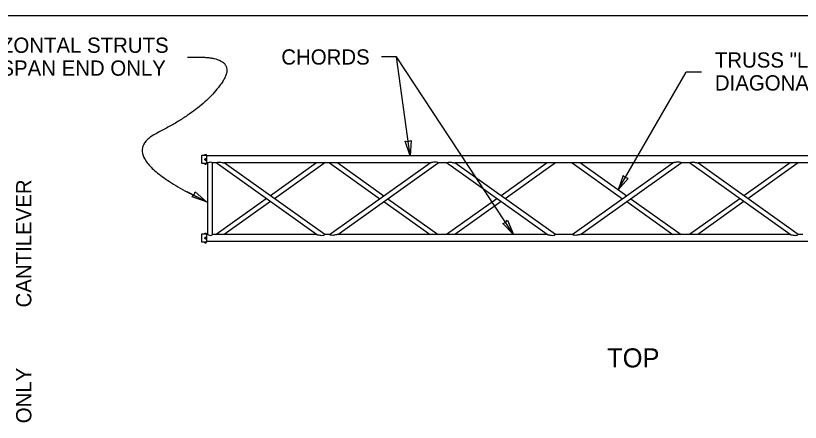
# Model space of a CAD drawing. Extents: x 99862 to 104211, y 98939 to 111076.
# Drawn here: x 100725 to 101548, y 101648 to 102075 of the extents above; entities that cross this region are included whole.
import ezdxf

# ---------------------------------------------------------------- set-up
doc = ezdxf.new("R2010")
doc.units = 0
for name, color, linetype in [('Level 14', 7, 'Continuous'), ('Level 15', 7, 'Continuous'), ('Level 20', 7, 'Continuous'), ('Level 6', 7, 'Continuous'), ('Level 60', 7, 'Continuous'), ('Level 62', 7, 'Continuous'), ('Level 9', 7, 'Continuous')]:
    doc.layers.add(name, color=color, linetype=linetype)

msp = doc.modelspace()

# ---------------------------------------------------------------- linework, layer by layer
at = {"layer": 'Level 14'}
msp.add_line((100905.36, 102031.62), (100913.36, 102031.62), dxfattribs=at)
msp.add_open_spline([(100913.36, 102031.62), (100960.09, 102032.22), (100921.98, 101976.24), (100824.85, 101927.65), (100925.31, 101879.73)], degree=2, dxfattribs=at)
at = {"layer": 'Level 15'}
for p, q in [((101124.65, 102031.68), (101108.65, 102031.68)), ((101138.85, 101927.97), (101124.65, 102031.68)), ((101247.26, 101845.47), (101124.65, 102031.68)), ((101357.15, 101892.22), (101428.52, 102015.84)), ((101444.52, 102015.84), (101428.52, 102015.84)), ((100926.54, 101879.04), (100904.98, 101890.24))]:
    msp.add_line(p, q, dxfattribs=at)
for points in [[(101138.85, 101927.97), (101133.77, 101943.17), (101136.92, 101942.84), (101139.89, 101943.96)], [(101357.15, 101892.22), (101367.69, 101904.3), (101364.65, 101905.21), (101362.34, 101907.38)], [(100925.31, 101879.73), (100910.15, 101884.92), (100912.32, 101887.23), (100913.23, 101890.26)], [(101247.26, 101845.47), (101235.99, 101856.86), (101238.96, 101857.96), (101241.13, 101860.27)]]:
    msp.add_lwpolyline(points, close=True, dxfattribs=at)
at = {"layer": 'Level 6'}
for p, q in [((100920.37, 101919.84), (100920.37, 101928.59)), ((100920.37, 101928.59), (100923.42, 101928.59)), ((100924.83, 101928.59), (100925.37, 101928.59)), ((100925.37, 101919.84), (100925.37, 101928.59)), ((101808.38, 101927.97), (100925.37, 101927.97)), ((100923.42, 101919.84), (100920.37, 101919.84)), ((100925.37, 101919.84), (100924.83, 101919.84)), ((100926.62, 101920.47), (100925.37, 101920.47)), ((100926.62, 101845.47), (100926.62, 101920.47)), ((100931.62, 101845.47), (100931.62, 101920.47)), ((100935.2, 101920.47), (100931.62, 101920.47)), ((101040.7, 101845.47), (100935.2, 101920.47)), ((101049.33, 101845.47), (100943.83, 101920.47)), ((101159.74, 101920.47), (100943.83, 101920.47)), ((101040.7, 101920.47), (100992.27, 101886.04)), ((101049.33, 101920.47), (100996.58, 101882.97)), ((101054.24, 101920.47), (101106.99, 101882.97)), ((101054.24, 101845.47), (101159.74, 101920.47)), ((101062.87, 101920.47), (101111.31, 101886.04)), ((101062.87, 101845.47), (101168.37, 101920.47)), ((101177.17, 101920.47), (101168.37, 101920.47)), ((101282.66, 101845.47), (101177.17, 101920.47)), ((101291.29, 101845.47), (101185.79, 101920.47)), ((101414.53, 101920.47), (101185.79, 101920.47)), ((101282.66, 101920.47), (101234.23, 101886.04)), ((101291.29, 101920.47), (101238.54, 101882.97)), ((101309.04, 101920.47), (101361.78, 101882.97)), ((101309.04, 101845.47), (101414.53, 101920.47)), ((101317.66, 101920.47), (101366.1, 101886.04)), ((101317.66, 101845.47), (101423.16, 101920.47)), ((101431.96, 101920.47), (101423.16, 101920.47)), ((101537.46, 101845.47), (101431.96, 101920.47)), ((101546.08, 101845.47), (101440.59, 101920.47)), ((101656.49, 101920.47), (101440.59, 101920.47)), ((101537.46, 101920.47), (101489.02, 101886.04)), ((101546.08, 101920.47), (101493.34, 101882.97)), ((100987.95, 101882.97), (100935.2, 101845.47)), ((101115.62, 101882.97), (101168.37, 101845.47)), ((101229.91, 101882.97), (101177.17, 101845.47)), ((101370.41, 101882.97), (101423.16, 101845.47)), ((101484.71, 101882.97), (101431.96, 101845.47)), ((100992.27, 101879.9), (100943.83, 101845.47)), ((101111.31, 101879.9), (101159.74, 101845.47)), ((101234.23, 101879.9), (101185.79, 101845.47)), ((101366.1, 101879.9), (101414.53, 101845.47)), ((101489.02, 101879.9), (101440.59, 101845.47)), ((100920.37, 101837.34), (100920.37, 101846.09)), ((100920.37, 101846.09), (100923.42, 101846.09)), ((100924.83, 101846.09), (100925.37, 101846.09)), ((100925.37, 101837.34), (100925.37, 101846.09)), ((100926.62, 101845.47), (100925.37, 101845.47)), ((101040.7, 101845.47), (100931.62, 101845.47)), ((101054.24, 101845.47), (101049.33, 101845.47)), ((101282.66, 101845.47), (101062.87, 101845.47)), ((101309.04, 101845.47), (101291.29, 101845.47)), ((101537.46, 101845.47), (101317.66, 101845.47)), ((101551, 101845.47), (101546.08, 101845.47)), ((100923.42, 101837.34), (100920.37, 101837.34)), ((100925.37, 101837.34), (100924.83, 101837.34)), ((101808.38, 101837.97), (100925.37, 101837.97))]:
    msp.add_line(p, q, dxfattribs=at)
for points, degree in [([(100923.66, 101928.59), (100923.66, 101928.59), (100923.66, 101928.59), (100923.67, 101928.59), (100923.68, 101928.59), (100923.7, 101928.59), (100923.73, 101928.59), (100923.76, 101928.58), (100923.79, 101928.58), (100923.83, 101928.58), (100923.87, 101928.58), (100923.92, 101928.57), (100923.97, 101928.57), (100924.02, 101928.57), (100924.07, 101928.57), (100924.13, 101928.57), (100924.18, 101928.57), (100924.23, 101928.57), (100924.28, 101928.57), (100924.33, 101928.57), (100924.38, 101928.58), (100924.42, 101928.58), (100924.46, 101928.58), (100924.49, 101928.58), (100924.52, 101928.59), (100924.55, 101928.59), (100924.57, 101928.59), (100924.58, 101928.59), (100924.59, 101928.59), (100924.59, 101928.59), (100924.59, 101928.59)], 3), ([(100924.59, 101919.84), (100924.59, 101919.84), (100924.58, 101919.84), (100924.57, 101919.85), (100924.55, 101919.85), (100924.52, 101919.85), (100924.49, 101919.85), (100924.46, 101919.86), (100924.42, 101919.86), (100924.37, 101919.86), (100924.33, 101919.86), (100924.28, 101919.87), (100924.23, 101919.87), (100924.18, 101919.87), (100924.12, 101919.87), (100924.07, 101919.87), (100924.02, 101919.87), (100923.97, 101919.87), (100923.92, 101919.86), (100923.87, 101919.86), (100923.83, 101919.86), (100923.79, 101919.86), (100923.76, 101919.85), (100923.73, 101919.85), (100923.7, 101919.85), (100923.68, 101919.85), (100923.66, 101919.84), (100923.66, 101919.84), (100923.66, 101919.84), (100923.66, 101919.84), (100923.66, 101919.84)], 3), ([(100926.62, 101920.47), (100926.66, 101920.44), (100926.77, 101920.71), (100929.59, 101922.12), (100931.48, 101920.48), (100931.6, 101920.51), (100931.62, 101920.47), (100931.62, 101920.47), (100931.62, 101920.47)], 3), ([(100926.64, 101920.48), (100926.63, 101920.47), (100926.63, 101920.47), (100926.62, 101920.47)], 2), ([(100931.62, 101920.47), (100931.62, 101920.47), (100931.62, 101920.47), (100931.62, 101920.47)], 2), ([(100935.2, 101920.47), (100935.2, 101920.47), (100935.23, 101920.46), (100935.36, 101920.7), (100936.76, 101921.45), (100939.48, 101921.41), (100941.21, 101921.09), (100942.66, 101920.75), (100943, 101920.67), (100943.29, 101920.6), (100943.53, 101920.54), (100943.7, 101920.5), (100943.79, 101920.48), (100943.83, 101920.47), (100943.83, 101920.47), (100943.83, 101920.47)], 3), ([(100935.21, 101920.47), (100935.21, 101920.47), (100935.2, 101920.47), (100935.2, 101920.47)], 2), ([(100943.83, 101920.47), (100943.83, 101920.47), (100943.83, 101920.47), (100943.82, 101920.47)], 2), ([(101168.37, 101920.47), (101168.37, 101920.47), (101168.35, 101920.46), (101168.21, 101920.7), (101166.82, 101921.45), (101164.1, 101921.41), (101162.37, 101921.09), (101160.92, 101920.75), (101160.57, 101920.67), (101160.28, 101920.6), (101160.05, 101920.54), (101159.87, 101920.5), (101159.78, 101920.48), (101159.75, 101920.47), (101159.74, 101920.47), (101159.74, 101920.47)], 3), ([(101159.74, 101920.47), (101159.74, 101920.47), (101159.74, 101920.47), (101159.75, 101920.47)], 2), ([(101168.37, 101920.47), (101168.37, 101920.47), (101168.37, 101920.47), (101168.37, 101920.47)], 2), ([(101177.17, 101920.47), (101177.16, 101920.47), (101177.19, 101920.46), (101177.32, 101920.7), (101178.72, 101921.45), (101181.44, 101921.41), (101183.17, 101921.09), (101184.62, 101920.75), (101184.96, 101920.67), (101185.25, 101920.6), (101185.49, 101920.54), (101185.66, 101920.5), (101185.75, 101920.48), (101185.79, 101920.47), (101185.79, 101920.47), (101185.79, 101920.47)], 3), ([(101177.17, 101920.47), (101177.17, 101920.47), (101177.17, 101920.47), (101177.17, 101920.47)], 2), ([(101185.79, 101920.47), (101185.79, 101920.47), (101185.79, 101920.47), (101185.79, 101920.47)], 2), ([(101423.16, 101920.47), (101423.16, 101920.47), (101423.14, 101920.46), (101423, 101920.7), (101421.61, 101921.45), (101418.89, 101921.41), (101417.16, 101921.09), (101415.71, 101920.75), (101415.37, 101920.67), (101415.07, 101920.6), (101414.84, 101920.54), (101414.66, 101920.5), (101414.57, 101920.48), (101414.54, 101920.47), (101414.53, 101920.47), (101414.53, 101920.47)], 3), ([(101414.53, 101920.47), (101414.53, 101920.47), (101414.54, 101920.47), (101414.54, 101920.47)], 2), ([(101423.16, 101920.47), (101423.16, 101920.47), (101423.16, 101920.47), (101423.16, 101920.47)], 2), ([(101431.96, 101920.47), (101431.96, 101920.47), (101431.98, 101920.46), (101432.12, 101920.7), (101433.51, 101921.45), (101436.23, 101921.41), (101437.96, 101921.09), (101439.41, 101920.75), (101439.75, 101920.67), (101440.05, 101920.6), (101440.28, 101920.54), (101440.46, 101920.5), (101440.55, 101920.48), (101440.58, 101920.47), (101440.59, 101920.47), (101440.59, 101920.47)], 3), ([(101431.96, 101920.47), (101431.96, 101920.47), (101431.96, 101920.47), (101431.96, 101920.47)], 2), ([(101440.59, 101920.47), (101440.59, 101920.47), (101440.58, 101920.47), (101440.58, 101920.47)], 2), ([(100923.66, 101846.09), (100923.66, 101846.09), (100923.66, 101846.09), (100923.67, 101846.09), (100923.68, 101846.09), (100923.7, 101846.09), (100923.73, 101846.09), (100923.76, 101846.08), (100923.79, 101846.08), (100923.83, 101846.08), (100923.87, 101846.08), (100923.92, 101846.07), (100923.97, 101846.07), (100924.02, 101846.07), (100924.07, 101846.07), (100924.13, 101846.07), (100924.18, 101846.07), (100924.23, 101846.07), (100924.28, 101846.07), (100924.33, 101846.07), (100924.38, 101846.08), (100924.42, 101846.08), (100924.46, 101846.08), (100924.49, 101846.08), (100924.52, 101846.09), (100924.55, 101846.09), (100924.57, 101846.09), (100924.58, 101846.09), (100924.59, 101846.09), (100924.59, 101846.09), (100924.59, 101846.09)], 3), ([(100926.62, 101845.47), (100926.66, 101845.5), (100926.77, 101845.23), (100929.59, 101843.81), (100931.48, 101845.46), (100931.6, 101845.43), (100931.62, 101845.47), (100931.62, 101845.47), (100931.62, 101845.47)], 3), ([(100926.64, 101845.46), (100926.63, 101845.47), (100926.63, 101845.47), (100926.62, 101845.47)], 2), ([(100931.62, 101845.47), (100931.62, 101845.47), (100931.62, 101845.47), (100931.62, 101845.47)], 2), ([(101040.74, 101845.46), (101040.72, 101845.47), (101040.71, 101845.47), (101040.7, 101845.47)], 2), ([(101040.7, 101845.47), (101040.71, 101845.47), (101040.72, 101845.46), (101040.83, 101845.44), (101041.01, 101845.39), (101041.24, 101845.34), (101041.53, 101845.26), (101041.88, 101845.18), (101042.27, 101845.09), (101043.88, 101844.77), (101045.86, 101844.34), (101048.55, 101844.77), (101049.3, 101845.45), (101049.32, 101845.46), (101049.33, 101845.47), (101049.33, 101845.47)], 3), ([(101049.33, 101845.47), (101049.33, 101845.47), (101049.33, 101845.47), (101049.32, 101845.47)], 2), ([(101054.24, 101845.47), (101054.24, 101845.47), (101054.25, 101845.47), (101054.25, 101845.47)], 2), ([(101062.87, 101845.47), (101062.87, 101845.47), (101062.85, 101845.46), (101062.74, 101845.44), (101062.57, 101845.39), (101062.33, 101845.34), (101062.04, 101845.26), (101061.69, 101845.18), (101061.3, 101845.09), (101059.69, 101844.77), (101057.72, 101844.34), (101055.02, 101844.77), (101054.27, 101845.45), (101054.25, 101845.46), (101054.24, 101845.47), (101054.24, 101845.47)], 3), ([(101062.84, 101845.46), (101062.86, 101845.47), (101062.87, 101845.47), (101062.87, 101845.47)], 2), ([(101282.7, 101845.46), (101282.68, 101845.47), (101282.67, 101845.47), (101282.66, 101845.47)], 2), ([(101282.66, 101845.47), (101282.67, 101845.47), (101282.68, 101845.46), (101282.8, 101845.44), (101282.97, 101845.39), (101283.2, 101845.34), (101283.5, 101845.26), (101283.84, 101845.18), (101284.23, 101845.09), (101285.85, 101844.77), (101287.82, 101844.34), (101290.51, 101844.77), (101291.26, 101845.45), (101291.28, 101845.46), (101291.29, 101845.47), (101291.29, 101845.47)], 3), ([(101291.29, 101845.47), (101291.29, 101845.47), (101291.29, 101845.47), (101291.28, 101845.47)], 2), ([(101309.04, 101845.47), (101309.04, 101845.47), (101309.04, 101845.47), (101309.04, 101845.47)], 2), ([(101317.66, 101845.47), (101317.66, 101845.47), (101317.64, 101845.46), (101317.53, 101845.44), (101317.36, 101845.39), (101317.12, 101845.34), (101316.83, 101845.26), (101316.49, 101845.18), (101316.09, 101845.09), (101314.48, 101844.77), (101312.51, 101844.34), (101309.81, 101844.77), (101309.06, 101845.45), (101309.04, 101845.46), (101309.04, 101845.47), (101309.04, 101845.47)], 3), ([(101317.66, 101845.47), (101317.66, 101845.47), (101317.66, 101845.47), (101317.66, 101845.47)], 2), ([(101537.49, 101845.46), (101537.47, 101845.47), (101537.46, 101845.47), (101537.46, 101845.47)], 2), ([(101537.46, 101845.47), (101537.46, 101845.47), (101537.48, 101845.46), (101537.59, 101845.44), (101537.76, 101845.39), (101538, 101845.34), (101538.29, 101845.26), (101538.63, 101845.18), (101539.03, 101845.09), (101540.64, 101844.77), (101542.61, 101844.34), (101545.31, 101844.77), (101546.06, 101845.45), (101546.08, 101845.46), (101546.08, 101845.47), (101546.08, 101845.47)], 3), ([(101546.08, 101845.47), (101546.08, 101845.47), (101546.08, 101845.47), (101546.08, 101845.47)], 2), ([(100924.59, 101837.34), (100924.59, 101837.34), (100924.58, 101837.34), (100924.57, 101837.35), (100924.55, 101837.35), (100924.52, 101837.35), (100924.49, 101837.35), (100924.46, 101837.36), (100924.42, 101837.36), (100924.37, 101837.36), (100924.33, 101837.36), (100924.28, 101837.37), (100924.23, 101837.37), (100924.18, 101837.37), (100924.12, 101837.37), (100924.07, 101837.37), (100924.02, 101837.37), (100923.97, 101837.37), (100923.92, 101837.36), (100923.87, 101837.36), (100923.83, 101837.36), (100923.79, 101837.36), (100923.76, 101837.35), (100923.73, 101837.35), (100923.7, 101837.35), (100923.68, 101837.35), (100923.66, 101837.34), (100923.66, 101837.34), (100923.66, 101837.34), (100923.66, 101837.34), (100923.66, 101837.34)], 3)]:
    msp.add_open_spline(points, degree=degree, dxfattribs=at)
at = {"layer": 'Level 60'}
msp.add_line((103150, 102075), (100000, 102075), dxfattribs=at)
at = {"layer": 'Level 62'}
for points in [[(100924.12, 101919.84), (100924, 101919.85), (100923.87, 101919.85), (100923.79, 101919.86)], [(100924.12, 101837.34), (100924, 101837.35), (100923.87, 101837.35), (100923.79, 101837.36)]]:
    msp.add_open_spline(points, degree=2, dxfattribs=at)
at = {"layer": 'Level 9'}
for p, q in [((100923.42, 101929.22), (100923.76, 101929.22)), ((100923.42, 101929.16), (100923.42, 101928.59)), ((100923.42, 101928.59), (100924.12, 101928.59)), ((100923.76, 101929.22), (100923.79, 101929.22)), ((100923.79, 101929.22), (100924.46, 101929.22)), ((100924.12, 101929.16), (100924.12, 101928.59)), ((100924.12, 101928.59), (100924.83, 101928.59)), ((100924.46, 101929.22), (100924.49, 101929.22)), ((100924.48, 101924.82), (100924.47, 101924.83)), ((100924.49, 101929.22), (100924.83, 101929.22)), ((100924.83, 101929.16), (100924.83, 101928.59)), ((100924.83, 101924.2), (100924.83, 101924.24)), ((100923.42, 101919.28), (100923.42, 101919.84)), ((100924.12, 101919.84), (100923.42, 101919.84)), ((100923.42, 101919.22), (100924.47, 101919.22)), ((100923.76, 101923.62), (100923.79, 101923.6)), ((100924.83, 101919.84), (100924.12, 101919.84)), ((100924.12, 101919.28), (100924.12, 101919.84)), ((100924.46, 101923.6), (100924.49, 101923.62)), ((100924.48, 101919.22), (100924.47, 101919.22)), ((100924.48, 101919.22), (100924.83, 101919.22)), ((100924.83, 101919.28), (100924.83, 101919.84)), ((100923.42, 101846.72), (100923.76, 101846.72)), ((100923.42, 101846.66), (100923.42, 101846.09)), ((100923.42, 101846.09), (100924.12, 101846.09)), ((100923.76, 101846.72), (100923.79, 101846.72)), ((100923.79, 101846.72), (100924.46, 101846.72)), ((100924.12, 101846.66), (100924.12, 101846.09)), ((100924.12, 101846.09), (100924.83, 101846.09)), ((100924.46, 101846.72), (100924.49, 101846.72)), ((100924.48, 101842.32), (100924.47, 101842.33)), ((100924.49, 101846.72), (100924.83, 101846.72)), ((100924.83, 101846.66), (100924.83, 101846.09)), ((100924.83, 101841.7), (100924.83, 101841.74)), ((100923.42, 101836.78), (100923.42, 101837.34)), ((100924.12, 101837.34), (100923.42, 101837.34)), ((100923.42, 101836.72), (100924.47, 101836.72)), ((100923.76, 101841.12), (100923.79, 101841.1)), ((100924.83, 101837.34), (100924.12, 101837.34)), ((100924.12, 101836.78), (100924.12, 101837.34)), ((100924.46, 101841.1), (100924.49, 101841.12)), ((100924.48, 101836.72), (100924.47, 101836.72)), ((100924.48, 101836.72), (100924.83, 101836.72)), ((100924.83, 101836.78), (100924.83, 101837.34))]:
    msp.add_line(p, q, dxfattribs=at)
for centre, start, end in [((100924.12, 101924.22), 60.75538, 180), ((100924.12, 101924.22), 180, 238.8031), ((100924.12, 101924.22), 1.41676, 59.24201), ((100924.12, 101924.22), 301.56083, 358.58324), ((100924.12, 101924.22), 241.1969, 298.43917), ((100924.12, 101841.72), 60.75538, 180), ((100924.12, 101841.72), 180, 238.8031), ((100924.12, 101841.72), 1.41676, 59.24201), ((100924.12, 101841.72), 301.56083, 358.58324), ((100924.12, 101841.72), 241.1969, 298.43917)]:
    msp.add_arc(centre, 0.703, start, end, dxfattribs=at)
for points, degree in [([(100923.42, 101929.22), (100923.42, 101929.22), (100923.42, 101929.22), (100923.42, 101929.22)], 2), ([(100923.42, 101929.16), (100923.42, 101929.19), (100923.42, 101929.22), (100923.42, 101929.22)], 2), ([(100923.42, 101929.16), (100923.53, 101929.19), (100923.65, 101929.22), (100923.76, 101929.22)], 2), ([(100924.12, 101925.03), (100924, 101924.96), (100923.88, 101924.89), (100923.75, 101924.81), (100923.64, 101924.75), (100923.53, 101924.69), (100923.42, 101924.62)], 3), ([(100923.42, 101924.22), (100923.42, 101924.36), (100923.42, 101924.49), (100923.42, 101924.62)], 2), ([(100923.42, 101923.81), (100923.42, 101923.94), (100923.42, 101924.08), (100923.42, 101924.22)], 2), ([(100923.42, 101923.81), (100923.53, 101923.75), (100923.65, 101923.68), (100923.76, 101923.62)], 2), ([(100923.79, 101929.22), (100923.79, 101929.22), (100923.79, 101929.22), (100923.8, 101929.22), (100923.91, 101929.22), (100924.02, 101929.19), (100924.12, 101929.16)], 3), ([(100924.12, 101929.16), (100924.23, 101929.19), (100924.35, 101929.22), (100924.46, 101929.22)], 2), ([(100924.47, 101924.83), (100924.46, 101924.84), (100924.46, 101924.84), (100924.45, 101924.84), (100924.34, 101924.91), (100924.23, 101924.97), (100924.12, 101925.03)], 3), ([(100924.83, 101924.62), (100924.72, 101924.69), (100924.6, 101924.76), (100924.48, 101924.82)], 2), ([(100924.49, 101929.22), (100924.5, 101929.22), (100924.5, 101929.22), (100924.5, 101929.22), (100924.61, 101929.22), (100924.72, 101929.19), (100924.83, 101929.16)], 3), ([(100924.49, 101923.62), (100924.5, 101923.62), (100924.5, 101923.62), (100924.5, 101923.62), (100924.61, 101923.69), (100924.72, 101923.75), (100924.83, 101923.81)], 3), ([(100924.83, 101929.16), (100924.83, 101929.19), (100924.83, 101929.22), (100924.83, 101929.22)], 2), ([(100924.83, 101924.24), (100924.83, 101924.37), (100924.83, 101924.5), (100924.83, 101924.62)], 2), ([(100924.83, 101923.81), (100924.83, 101923.94), (100924.83, 101924.07), (100924.83, 101924.2)], 2), ([(100923.42, 101919.22), (100923.42, 101919.22), (100923.42, 101919.24), (100923.42, 101919.28)], 2), ([(100924.12, 101919.28), (100924, 101919.24), (100923.88, 101919.22), (100923.75, 101919.22), (100923.64, 101919.22), (100923.53, 101919.25), (100923.42, 101919.28)], 3), ([(100923.42, 101919.22), (100923.42, 101919.22), (100923.42, 101919.22), (100923.42, 101919.22)], 2), ([(100923.79, 101923.6), (100923.79, 101923.6), (100923.79, 101923.6), (100923.8, 101923.6), (100923.91, 101923.53), (100924.02, 101923.47), (100924.12, 101923.41)], 3), ([(100923.79, 101919.22), (100923.79, 101919.22), (100923.79, 101919.22), (100923.79, 101919.22)], 2), ([(100924.12, 101923.41), (100924.23, 101923.47), (100924.35, 101923.53), (100924.46, 101923.6)], 2), ([(100924.47, 101919.22), (100924.46, 101919.22), (100924.46, 101919.22), (100924.45, 101919.22), (100924.34, 101919.22), (100924.23, 101919.25), (100924.12, 101919.28)], 3), ([(100924.83, 101919.28), (100924.72, 101919.24), (100924.6, 101919.22), (100924.48, 101919.22)], 2), ([(100924.83, 101919.22), (100924.83, 101919.22), (100924.83, 101919.24), (100924.83, 101919.28)], 2), ([(100923.42, 101846.72), (100923.42, 101846.72), (100923.42, 101846.72), (100923.42, 101846.72)], 2), ([(100923.42, 101846.66), (100923.42, 101846.69), (100923.42, 101846.72), (100923.42, 101846.72)], 2), ([(100923.42, 101846.66), (100923.53, 101846.69), (100923.65, 101846.72), (100923.76, 101846.72)], 2), ([(100924.12, 101842.53), (100924, 101842.46), (100923.88, 101842.39), (100923.75, 101842.31), (100923.64, 101842.25), (100923.53, 101842.19), (100923.42, 101842.12)], 3), ([(100923.42, 101841.72), (100923.42, 101841.86), (100923.42, 101841.99), (100923.42, 101842.12)], 2), ([(100923.42, 101841.31), (100923.42, 101841.44), (100923.42, 101841.58), (100923.42, 101841.72)], 2), ([(100923.79, 101846.72), (100923.79, 101846.72), (100923.79, 101846.72), (100923.8, 101846.72), (100923.91, 101846.72), (100924.02, 101846.69), (100924.12, 101846.66)], 3), ([(100924.12, 101846.66), (100924.23, 101846.69), (100924.35, 101846.72), (100924.46, 101846.72)], 2), ([(100924.47, 101842.33), (100924.46, 101842.34), (100924.46, 101842.34), (100924.45, 101842.34), (100924.34, 101842.41), (100924.23, 101842.47), (100924.12, 101842.53)], 3), ([(100924.83, 101842.12), (100924.72, 101842.19), (100924.6, 101842.26), (100924.48, 101842.32)], 2), ([(100924.49, 101846.72), (100924.5, 101846.72), (100924.5, 101846.72), (100924.5, 101846.72), (100924.61, 101846.72), (100924.72, 101846.69), (100924.83, 101846.66)], 3), ([(100924.83, 101846.66), (100924.83, 101846.69), (100924.83, 101846.72), (100924.83, 101846.72)], 2), ([(100924.83, 101841.74), (100924.83, 101841.87), (100924.83, 101842), (100924.83, 101842.12)], 2), ([(100924.83, 101841.31), (100924.83, 101841.44), (100924.83, 101841.57), (100924.83, 101841.7)], 2), ([(100923.42, 101841.31), (100923.53, 101841.25), (100923.65, 101841.18), (100923.76, 101841.12)], 2), ([(100923.42, 101836.72), (100923.42, 101836.72), (100923.42, 101836.74), (100923.42, 101836.78)], 2), ([(100924.12, 101836.78), (100924, 101836.74), (100923.88, 101836.72), (100923.75, 101836.72), (100923.64, 101836.72), (100923.53, 101836.75), (100923.42, 101836.78)], 3), ([(100923.79, 101841.1), (100923.79, 101841.1), (100923.79, 101841.1), (100923.8, 101841.1), (100923.91, 101841.03), (100924.02, 101840.97), (100924.12, 101840.91)], 3), ([(100923.79, 101836.72), (100923.79, 101836.72), (100923.79, 101836.72), (100923.79, 101836.72)], 2), ([(100924.12, 101840.91), (100924.23, 101840.97), (100924.35, 101841.03), (100924.46, 101841.1)], 2), ([(100924.47, 101836.72), (100924.46, 101836.72), (100924.46, 101836.72), (100924.45, 101836.72), (100924.34, 101836.72), (100924.23, 101836.75), (100924.12, 101836.78)], 3), ([(100924.83, 101836.78), (100924.72, 101836.74), (100924.6, 101836.72), (100924.48, 101836.72)], 2), ([(100924.49, 101841.12), (100924.5, 101841.12), (100924.5, 101841.12), (100924.5, 101841.12), (100924.61, 101841.19), (100924.72, 101841.25), (100924.83, 101841.31)], 3), ([(100924.83, 101836.72), (100924.83, 101836.72), (100924.83, 101836.74), (100924.83, 101836.78)], 2)]:
    msp.add_open_spline(points, degree=degree, dxfattribs=at)

# ---------------------------------------------------------------- texts
at = {"layer": 'Level 20'}
for s, height, rotation, p in [('HORIZONTAL STRUTS', 16, 360, (100656.04, 102036.03)), ('CHORDS', 16, 360, (101003.68, 102023.68)), ('TRUSS "LOWER" HORIZONTAL', 16, 360, (101458.61, 102020.5)), ('AT SPAN END ONLY', 16, 360, (100675.64, 102012.03)), ('DIAGONAL (TYP.)', 16, 360, (101458.61, 101996.5)), ('CANTILEVER', 16, 90, (100741.39, 101768.85)), ('TOP', 20, 360, (101345.53, 101705.93)), ('ONLY', 16, 90, (100741.39, 101647.31))]:
    msp.add_text(s, height=height, rotation=rotation, dxfattribs=at).set_placement(p)

doc.saveas('drawing.dxf')
